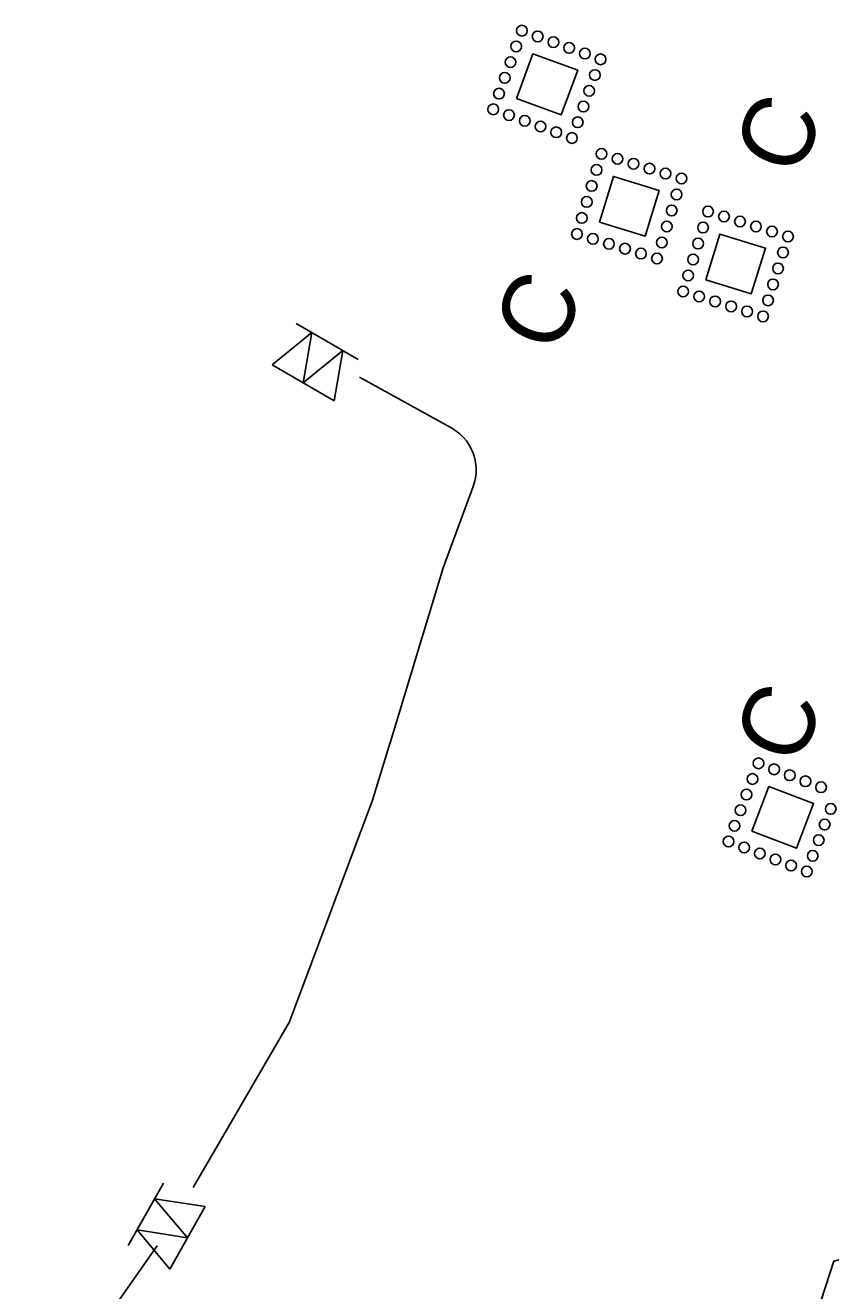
# Model space of a CAD drawing. Extents: x 2470000 to 2520000, y 340000 to 380000.
# Drawn here: x 2483067.2 to 2483235.5, y 368565.5 to 368830 of the extents above; entities that cross this region are included whole.
import ezdxf

# ---------------------------------------------------------------- set-up
doc = ezdxf.new("R2010")
doc.units = 0
for name, color, linetype in [('Prop Guardrail', 7, 'Continuous'), ('Scratch_Level_5', 7, 'Continuous'), ('Sheet Data Field CELL', 7, 'Continuous'), ('Special Sediment Control Fence Section Both CELL', 7, 'Continuous'), ('Temporary Silt Fence CG', 7, 'Continuous')]:
    doc.layers.add(name, color=color, linetype=linetype)

# ---------------------------------------------------------------- blocks, each defined once
blk = doc.blocks.new('C3')
at = {"layer": 'Prop Guardrail'}
blk.add_text('C', height=0.3, dxfattribs=at).set_placement((-0.161, -0.136))

msp = doc.modelspace()

# ---------------------------------------------------------------- linework, layer by layer
at = {"layer": 'Scratch_Level_5'}
for points in [[(2483169.8, 368814.66), (2483173.22, 368824.06), (2483182.62, 368820.64), (2483179.19, 368811.25)], [(2483187.16, 368788.86), (2483190.09, 368798.42), (2483199.65, 368795.49), (2483196.71, 368785.93)], [(2483209.37, 368776.81), (2483212.34, 368786.36), (2483221.89, 368783.39), (2483218.91, 368773.85)], [(2483219.01, 368661.54), (2483222.59, 368670.88), (2483231.92, 368667.31), (2483228.34, 368657.97)]]:
    msp.add_lwpolyline(points, close=True, dxfattribs=at)
for centre in [(2483170.96, 368828.87), (2483169.76, 368825.58), (2483174.25, 368827.67), (2483177.54, 368826.47), (2483180.83, 368825.27), (2483184.12, 368824.08), (2483187.4, 368822.88), (2483168.57, 368822.29), (2483167.37, 368819), (2483186.21, 368819.59), (2483166.17, 368815.71), (2483185.01, 368816.3), (2483164.97, 368812.42), (2483183.81, 368813.01), (2483168.26, 368811.22), (2483171.55, 368810.03), (2483182.62, 368809.72), (2483174.84, 368808.83), (2483178.13, 368807.63), (2483181.42, 368806.43), (2483187.59, 368803.11), (2483190.94, 368802.08), (2483186.56, 368799.76), (2483194.28, 368801.05), (2483197.63, 368800.03), (2483185.54, 368796.41), (2483200.97, 368799), (2483204.32, 368797.97), (2483203.29, 368794.63), (2483184.51, 368793.07), (2483202.27, 368791.28), (2483183.48, 368789.72), (2483209.86, 368791.06), (2483213.2, 368790.02), (2483216.54, 368788.97), (2483182.46, 368786.37), (2483201.24, 368787.93), (2483208.82, 368787.71), (2483219.88, 368787.93), (2483223.23, 368786.89), (2483226.57, 368785.85), (2483185.8, 368785.35), (2483189.15, 368784.32), (2483192.5, 368783.3), (2483200.21, 368784.59), (2483207.78, 368784.37), (2483195.84, 368782.27), (2483199.19, 368781.24), (2483206.74, 368781.03), (2483225.53, 368782.51), (2483224.49, 368779.17), (2483205.7, 368777.69), (2483223.45, 368775.83), (2483204.66, 368774.35), (2483208, 368773.31), (2483211.34, 368772.27), (2483214.68, 368771.23), (2483218.02, 368770.18), (2483222.4, 368772.49), (2483221.36, 368769.14), (2483220.4, 368675.72), (2483219.15, 368672.45), (2483223.67, 368674.47), (2483226.94, 368673.22), (2483230.21, 368671.97), (2483233.48, 368670.72), (2483217.9, 368669.19), (2483216.65, 368665.92), (2483235.5, 368666.2), (2483215.4, 368662.65), (2483234.24, 368662.93), (2483214.15, 368659.38), (2483232.99, 368659.66), (2483217.42, 368658.13), (2483220.68, 368656.88), (2483231.74, 368656.39), (2483223.95, 368655.62), (2483227.22, 368654.37), (2483230.49, 368653.12)]:
    msp.add_circle(centre, 1.12, dxfattribs=at)
at = {"layer": 'Sheet Data Field CELL'}
for p, q in [((2483155.82, 368746.04), (2483137.01, 368756.46)), ((2483154.5, 368716.58), (2483160.79, 368733.6)), ((2483143.45, 368680.03), (2483154.5, 368716.58)), ((2483139.7, 368668.04), (2483143.45, 368680.06)), ((2483122.23, 368621.31), (2483139.7, 368668.04)), ((2483102.22, 368587.04), (2483122.38, 368621.71)), ((2483067.16, 368535.66), (2483094.75, 368574.88))]:
    msp.add_line(p, q, dxfattribs=at)
msp.add_arc((2483151.4, 368737.06), 10, 339.7339, 63.8197, dxfattribs=at)
at = {"layer": 'Special Sediment Control Fence Section Both CELL'}
for p, q in [((2483123.81, 368767.69), (2483136.76, 368760.12)), ((2483118.77, 368759.05), (2483131.72, 368751.49)), ((2483088.66, 368574.92), (2483096.04, 368587.99)), ((2483097.37, 368570.01), (2483104.75, 368583.07))]:
    msp.add_line(p, q, dxfattribs=at)
for points in [[(2483118.77, 368759.05), (2483127.05, 368765.8), (2483125.24, 368755.27)], [(2483125.24, 368755.27), (2483133.52, 368762.01), (2483131.72, 368751.49)], [(2483101.06, 368576.54), (2483094.19, 368584.72), (2483104.75, 368583.07)], [(2483097.37, 368570.01), (2483090.51, 368578.19), (2483101.06, 368576.54)]]:
    msp.add_lwpolyline(points, dxfattribs=at)
at = {"layer": 'Temporary Silt Fence CG'}
msp.add_lwpolyline([(2483204.9, 368475.35), (2483236.12, 368571.69), (2483273.41, 368581.33), (2483305.92, 368598.47), (2483320.28, 368610.11)], dxfattribs=at)

# ---------------------------------------------------------------- block references
at = {"layer": 'Scratch_Level_5', "xscale": 50, "yscale": 49.99999999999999, "rotation": 67.56305879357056}
for p in [(2483225.45, 368807.87), (2483175.27, 368770.89), (2483225.47, 368684.74)]:
    msp.add_blockref('C3', p, dxfattribs=at)

doc.saveas('drawing.dxf')
